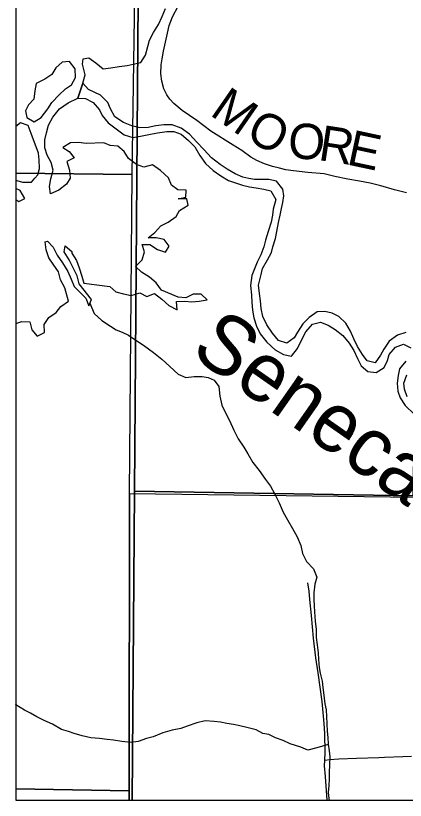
# Model space of a CAD drawing. Extents: x 0 to 191, y 0 to 55.
# Drawn here: x 184.17 to 184.796, y 47.92 to 49.18 of the extents above; entities that cross this region are included whole.
import ezdxf

# ---------------------------------------------------------------- set-up
doc = ezdxf.new("R2010")
doc.units = 0
for name, color, linetype in [('GM_X_Corporation', 7, 'Continuous'), ('GM_X_County_Road', 7, 'Continuous'), ('GM_X_County_Road_Text', 7, 'Continuous'), ('GM_X_Major_Lake', 7, 'Continuous'), ('GM_X_Minor_River', 7, 'Continuous'), ('GM_X_Minor_River_Text', 7, 'Continuous')]:
    doc.layers.add(name, color=color, linetype=linetype)

msp = doc.modelspace()

# ---------------------------------------------------------------- linework, layer by layer
at = {"layer": 'GM_X_Corporation'}
for points in [[(184.1701, 53.923), (184.1701, 47.9197), (186.2932, 47.9197), (186.2941, 48.012), (186.2991, 48.3871), (186.4921, 48.3828), (187.098, 48.377), (187.7625, 48.3707), (187.7657, 48.3707), (188.3304, 48.3653), (188.401, 48.3646), (188.9117, 48.3542), (189.3607, 48.345), (189.6849, 48.3383), (190.1514, 48.3336), (190.3574, 48.3286), (190.3641, 48.8031), (190.3751, 50.4761)], [(184.1701, 53.923), (184.1701, 49.9388), (184.171, 49.9388), (184.1826, 49.9387), (184.1847, 49.9387), (184.3733, 49.937), (184.3701, 49.6407), (184.3701, 49.6374), (184.3608, 48.4162), (184.8085, 48.4088), (184.8161, 48.8829), (184.8161, 48.8869), (184.8319, 50.3441), (184.8319, 50.3472), (184.8438, 50.7018)]]:
    msp.add_lwpolyline(points, dxfattribs=at)
for points in [[(184.1701, 49.9388), (184.1701, 47.9197), (184.357, 47.9197), (184.3608, 48.4162), (184.3701, 49.6374), (184.3701, 49.6407), (184.3733, 49.937), (184.1847, 49.9387), (184.1826, 49.9387), (184.171, 49.9388)], [(184.1701, 49.9382), (184.1701, 48.9269), (184.3573, 48.9248), (184.3647, 49.4297), (184.3713, 49.9361)], [(184.3647, 49.4297), (185.276, 49.4114), (185.2748, 48.3999), (184.3526, 48.412), (184.3573, 48.9248)], [(184.1701, 48.9269), (184.1701, 47.938), (184.3521, 47.9349), (184.3526, 48.412), (184.3573, 48.9248)], [(184.3521, 47.9197), (185.2718, 47.9197), (185.2748, 48.3999), (184.3526, 48.412), (184.3521, 47.9349)], [(184.357, 47.9197), (186.2932, 47.9197), (186.2941, 48.012), (186.2991, 48.3871), (186.1484, 48.3893), (186.1442, 48.3893), (185.2112, 48.4029), (185.207, 48.403), (184.8085, 48.4088), (184.3608, 48.4162)], [(184.1701, 47.938), (184.1701, 47.9197), (184.3521, 47.9197), (184.3521, 47.9349)]]:
    msp.add_lwpolyline(points, close=True, dxfattribs=at)
at = {"layer": 'GM_X_County_Road'}
for points in [[(184.7978, 48.8952), (184.7783, 48.9001), (184.7566, 48.9062), (184.7392, 48.9105), (184.7223, 48.9137), (184.7035, 48.9173), (184.6826, 48.9214), (184.6652, 48.9254), (184.6391, 48.9279), (184.6161, 48.9305), (184.6037, 48.9323), (184.5937, 48.9345), (184.5824, 48.9374), (184.5694, 48.9415), (184.5573, 48.9471), (184.5476, 48.9526), (184.533, 48.9631), (184.5191, 48.9717), (184.4835, 48.994), (184.4611, 49.0112), (184.4375, 49.0276), (184.4239, 49.0387), (184.4178, 49.0458), (184.4127, 49.0526), (184.4081, 49.062), (184.4048, 49.0742), (184.403, 49.086), (184.4036, 49.1008), (184.4052, 49.1102), (184.4072, 49.1225), (184.4139, 49.1513), (184.4164, 49.1636), (184.4218, 49.1779), (184.4399, 49.2127)], [(184.6667, 47.9844), (184.6668, 47.9967), (184.6663, 48.0271), (184.6654, 48.0429), (184.6621, 48.0783), (184.6559, 48.1245), (184.6522, 48.1487), (184.6483, 48.18), (184.6448, 48.2162), (184.6423, 48.2422), (184.6412, 48.2553), (184.6391, 48.269)], [(184.6667, 47.9844), (184.6743, 47.9854), (184.6892, 47.9865), (184.7174, 47.9871), (184.753, 47.9887), (184.7625, 47.9892), (184.7918, 47.9903), (184.8054, 47.9906)], [(184.6703, 47.9197), (184.6676, 47.9579), (184.6661, 47.9749), (184.6667, 47.9844)]]:
    msp.add_lwpolyline(points, dxfattribs=at)
at = {"layer": 'GM_X_Major_Lake'}
for p, q in [((184.27, 49.0471), (184.2779, 49.0715)), ((184.2794, 48.7499), (184.321, 48.7447))]:
    msp.add_line(p, q, dxfattribs=at)
for points in [[(184.2783, 49.1101), (184.2875, 49.112), (184.2989, 49.1041), (184.3107, 49.0942), (184.3228, 49.0958), (184.3361, 49.0981), (184.349, 49.0996), (184.3585, 49.1019), (184.371, 49.1042), (184.3786, 49.1163), (184.3823, 49.13), (184.385, 49.1403), (184.3914, 49.1524), (184.3994, 49.1653), (184.4054, 49.1782), (184.4107, 49.1911)], [(184.2551, 49.0654), (184.2597, 49.0687), (184.2662, 49.0805), (184.2654, 49.0942), (184.2562, 49.1059), (184.2449, 49.1051), (184.2343, 49.096), (184.2282, 49.0853), (184.2168, 49.0777), (184.2032, 49.0708), (184.2006, 49.0591), (184.1991, 49.0458), (184.1904, 49.0363), (184.1858, 49.0268)], [(184.2779, 49.0715), (184.2817, 49.0848), (184.2773, 49.1018), (184.2783, 49.1101)], [(184.1858, 49.0268), (184.1878, 49.0161), (184.1995, 49.0093), (184.2109, 49.0162), (184.2219, 49.0299), (184.2283, 49.0402), (184.2397, 49.0524), (184.2503, 49.0619), (184.2551, 49.0654)], [(184.4042, 48.7391), (184.3954, 48.7505), (184.3848, 48.7596), (184.3723, 48.7675), (184.3624, 48.7766), (184.373, 48.7873), (184.3768, 48.8002), (184.373, 48.8123), (184.3855, 48.8123), (184.3977, 48.8044), (184.4106, 48.7999), (184.4163, 48.8094), (184.4087, 48.8203), (184.3958, 48.823), (184.3829, 48.823), (184.3935, 48.8317), (184.403, 48.8424), (184.4151, 48.8481), (184.428, 48.8572), (184.4333, 48.8667), (184.447, 48.8754), (184.4447, 48.8853), (184.431, 48.8857), (184.4435, 48.888), (184.4439, 48.8993), (184.4306, 48.8997), (184.4204, 48.9073), (184.4155, 48.919), (184.4025, 48.9308), (184.3896, 48.9399), (184.376, 48.9364), (184.3639, 48.9406), (184.351, 48.9501), (184.3441, 48.9614), (184.3343, 48.9701), (184.3217, 48.9709), (184.3115, 48.9754), (184.2834, 48.9746), (184.2709, 48.9757), (184.258, 48.9753), (184.2459, 48.9677), (184.2561, 48.9617), (184.2641, 48.9514), (184.252, 48.9457), (184.2565, 48.9317), (184.2577, 48.9188), (184.2516, 48.9093), (184.2391, 48.8994), (184.2258, 48.8937), (184.2243, 48.9051), (184.2266, 48.9176), (184.2304, 48.9313), (184.2269, 48.9438), (184.2205, 48.9556), (184.2171, 48.9673), (184.2171, 48.9802), (184.2197, 48.9916), (184.2227, 49.0038), (184.2296, 49.0167), (184.2402, 49.03), (184.2542, 49.0399), (184.27, 49.0471)], [(184.2009, 48.9186), (184.2058, 48.9243), (184.2081, 48.9342), (184.2076, 48.9479), (184.2065, 48.9589), (184.203, 48.9691), (184.1988, 48.9801), (184.195, 48.9903), (184.1901, 49.0032), (184.1779, 49.0074), (184.1701, 49.0019)], [(184.1701, 48.916), (184.1717, 48.9151), (184.1812, 48.9121), (184.1956, 48.9125), (184.2009, 48.9186)], [(184.181, 48.8926), (184.1774, 48.8988), (184.1701, 48.9022)], [(184.1701, 48.8847), (184.1752, 48.8813), (184.1846, 48.8863), (184.181, 48.8926)], [(184.2172, 48.8163), (184.2213, 48.8174), (184.2304, 48.8079), (184.2369, 48.795), (184.2452, 48.7825), (184.2536, 48.7689), (184.2593, 48.7567), (184.2642, 48.7446)], [(184.2491, 48.7427), (184.2422, 48.7556), (184.2388, 48.7685), (184.2301, 48.7806), (184.2232, 48.7905), (184.2191, 48.8034), (184.2172, 48.8163)], [(184.2718, 48.7488), (184.2688, 48.7617), (184.2559, 48.7875), (184.2479, 48.8004), (184.2494, 48.8102), (184.2604, 48.8008)], [(184.2604, 48.8008), (184.2604, 48.7985), (184.2676, 48.7864), (184.2722, 48.7746), (184.276, 48.7613), (184.2794, 48.7499)], [(184.2642, 48.7446), (184.2827, 48.7259), (184.2874, 48.7135), (184.2918, 48.7241), (184.2718, 48.7488)], [(184.1701, 48.6854), (184.1798, 48.6887), (184.1927, 48.6878), (184.1959, 48.6749), (184.2044, 48.6652), (184.2161, 48.671), (184.2159, 48.6839), (184.2233, 48.695), (184.2353, 48.7032), (184.2427, 48.7128), (184.2551, 48.7213), (184.2491, 48.7427)], [(184.321, 48.7447), (184.3306, 48.7361), (184.3432, 48.7329), (184.3557, 48.7304), (184.3693, 48.7344), (184.3804, 48.7285), (184.3932, 48.7336), (184.4047, 48.7243), (184.4162, 48.7142), (184.4291, 48.7072), (184.4282, 48.7205), (184.4414, 48.7211), (184.4528, 48.7201), (184.4645, 48.7214), (184.4774, 48.7231), (184.4678, 48.7325), (184.4553, 48.7323), (184.4433, 48.7264), (184.4307, 48.7277), (184.4042, 48.7391)]]:
    msp.add_lwpolyline(points, dxfattribs=at)
at = {"layer": 'GM_X_Minor_River'}
msp.add_line((184.2779, 49.0715), (184.27, 49.0471), dxfattribs=at)
for points in [[(184.5599, 48.7467), (184.564, 48.7638), (184.5666, 48.7736), (184.5745, 48.7873), (184.5806, 48.7991), (184.5828, 48.8086), (184.587, 48.8219), (184.5896, 48.8333), (184.5919, 48.8474), (184.5945, 48.8595), (184.5967, 48.8698), (184.599, 48.8797), (184.6009, 48.8903), (184.599, 48.9009), (184.5891, 48.9138), (184.5765, 48.9168), (184.5538, 48.9167), (184.5443, 48.9182), (184.5348, 48.9204), (184.5226, 48.9257), (184.5097, 48.9329), (184.4983, 48.9404), (184.4843, 48.9514), (184.4721, 48.9647), (184.4607, 48.9764), (184.4489, 48.9896), (184.4356, 48.9991), (184.4215, 49.0044), (184.4082, 49.0043), (184.3953, 49.0027), (184.3828, 49.0001), (184.3692, 48.9996), (184.3563, 49.0026), (184.343, 49.0079), (184.3293, 49.0173), (184.3224, 49.0302), (184.3179, 49.0401), (184.3061, 49.0522), (184.2871, 49.0612), (184.2779, 49.0715)], [(184.27, 49.0471), (184.2822, 49.0468), (184.2947, 49.0404), (184.3046, 49.0286), (184.3088, 49.0192), (184.3183, 49.0074), (184.3316, 48.998), (184.3442, 48.9882), (184.3582, 48.984), (184.3707, 48.986), (184.384, 48.989), (184.3976, 48.9917), (184.4128, 48.9937), (184.4242, 48.9937), (184.436, 48.9892), (184.4478, 48.9794), (184.4577, 48.9692), (184.466, 48.9551), (184.4748, 48.9423), (184.487, 48.9309), (184.4995, 48.9222), (184.512, 48.9147), (184.5246, 48.9105), (184.5341, 48.9075), (184.5454, 48.9049), (184.5561, 48.903), (184.5686, 48.9012), (184.58, 48.8982), (184.5876, 48.8842), (184.5835, 48.869), (184.5827, 48.8595), (184.5801, 48.8481), (184.5756, 48.8329), (184.5711, 48.8192), (184.5684, 48.8082), (184.5639, 48.7957), (184.5579, 48.7839), (184.5533, 48.7732), (184.5492, 48.7622), (184.5473, 48.7465)], [(184.5473, 48.7465), (184.5489, 48.7311), (184.549, 48.7189), (184.5502, 48.7068), (184.5525, 48.6943), (184.5568, 48.6811), (184.5625, 48.6686), (184.5736, 48.6554), (184.5865, 48.6429), (184.6002, 48.6358), (184.6131, 48.6328), (184.6228, 48.6454), (184.6288, 48.6587), (184.6359, 48.6717), (184.6468, 48.6842), (184.6593, 48.6873), (184.6718, 48.6825), (184.6832, 48.6757), (184.6954, 48.6663), (184.7057, 48.6539), (184.7129, 48.6421), (184.7187, 48.6293), (184.7248, 48.6172), (184.7355, 48.6081), (184.7491, 48.6067), (184.7615, 48.6147), (184.7672, 48.6261), (184.7698, 48.6356), (184.7799, 48.6475), (184.7927, 48.6521), (184.8045, 48.6465)], [(184.7964, 48.6711), (184.7832, 48.6668), (184.77, 48.6569), (184.7614, 48.6443), (184.7561, 48.6344), (184.7475, 48.6219), (184.7346, 48.6252), (184.727, 48.6358), (184.719, 48.6486), (184.7128, 48.6607), (184.7078, 48.6728), (184.7002, 48.6861), (184.6888, 48.6966), (184.6782, 48.7019), (184.6664, 48.7045), (184.6543, 48.704), (184.6411, 48.6952), (184.6313, 48.6849), (184.6227, 48.6716), (184.6174, 48.6621), (184.6054, 48.6536), (184.5921, 48.6581), (184.5822, 48.6698), (184.5734, 48.683), (184.5669, 48.6963), (184.5642, 48.7095), (184.5634, 48.7217), (184.5618, 48.7336), (184.5599, 48.7467)], [(184.2893, 48.7181), (184.2963, 48.7015), (184.3084, 48.6902), (184.3221, 48.6812), (184.3316, 48.6752), (184.3411, 48.6714), (184.3513, 48.6666), (184.3631, 48.6587), (184.3753, 48.6504), (184.3916, 48.6387), (184.4049, 48.6278), (184.4175, 48.6161), (184.4312, 48.6037), (184.4433, 48.5984), (184.4566, 48.6), (184.4694, 48.6001), (184.4793, 48.5987), (184.4888, 48.5945), (184.4964, 48.584), (184.4976, 48.5688), (184.5011, 48.5544), (184.5076, 48.5408), (184.5134, 48.5298), (184.5206, 48.5143), (184.5272, 48.5003), (184.5363, 48.4867), (184.5428, 48.4761), (184.5509, 48.4621), (184.5608, 48.4493), (184.5711, 48.435), (184.5791, 48.424), (184.5863, 48.4111), (184.5929, 48.3971), (184.5998, 48.3824), (184.6066, 48.3699), (184.6143, 48.3563), (184.6223, 48.3427), (184.6277, 48.3287), (184.6304, 48.3162), (184.6373, 48.3033), (184.6484, 48.2913), (184.6537, 48.278), (184.6504, 48.2666), (184.649, 48.253), (184.6486, 48.2419), (184.6491, 48.2321), (184.6499, 48.2222), (184.6507, 48.2074), (184.6523, 48.1942), (184.6528, 48.1813), (184.654, 48.1691), (184.6556, 48.1566), (184.6564, 48.146), (184.6576, 48.1331), (184.6588, 48.1237), (184.6623, 48.1112), (184.6635, 48.1009), (184.6647, 48.0884), (184.6666, 48.0744), (184.6686, 48.0649), (184.669, 48.0543), (184.6695, 48.0425), (184.6703, 48.0308), (184.6715, 48.0206), (184.6719, 48.0099), (184.6735, 47.9993), (184.6747, 47.9895), (184.674, 47.9766), (184.6737, 47.9644), (184.6734, 47.9542), (184.6727, 47.9436), (184.6716, 47.9322), (184.6728, 47.9227), (184.6733, 47.9197)], [(184.7963, 48.6248), (184.7865, 48.6126), (184.784, 48.6016), (184.7825, 48.5894), (184.7837, 48.5766), (184.7876, 48.566), (184.7956, 48.5535), (184.8101, 48.5399)], [(184.7989, 48.5675), (184.7943, 48.5797), (184.7931, 48.5895), (184.7983, 48.6028)], [(184.672, 48.0094), (184.6534, 48.0038), (184.6391, 48.0003), (184.6277, 48.0051), (184.611, 48.0103), (184.5996, 48.0156), (184.5875, 48.0201), (184.5768, 48.0253), (184.567, 48.0271), (184.5564, 48.0328), (184.5412, 48.0365), (184.5302, 48.0394), (184.52, 48.0413), (184.509, 48.0431), (184.4991, 48.0453), (184.4885, 48.046), (184.4741, 48.0475), (184.4609, 48.044), (184.4454, 48.0386), (184.4352, 48.0351), (184.4212, 48.0324), (184.4065, 48.0281), (184.391, 48.0216), (184.3801, 48.0192), (184.3665, 48.0142), (184.3547, 48.0126), (184.3407, 48.0141), (184.3271, 48.0162), (184.3169, 48.0173), (184.3044, 48.0188), (184.2907, 48.0202), (184.2767, 48.0232), (184.2642, 48.0269), (184.2547, 48.0302), (184.2437, 48.0332), (184.2289, 48.0422), (184.216, 48.0478), (184.2042, 48.0535), (184.194, 48.0598), (184.1841, 48.0647), (184.1704, 48.073), (184.1701, 48.0733)]]:
    msp.add_lwpolyline(points, dxfattribs=at)

# ---------------------------------------------------------------- texts
at = {"layer": 'GM_X_County_Road_Text'}
for s, rotation, p in [('M', 325.2654, (184.4802, 49.021)), ('O', 331.9667, (184.5371, 48.9821)), ('O', 355.8412, (184.6059, 48.9515)), ('R', 351.2782, (184.6546, 48.948)), ('E', 347.9454, (184.6999, 48.9411))]:
    msp.add_text(s, height=0.0568, rotation=rotation, dxfattribs=at).set_placement(p)
at = {"layer": 'GM_X_Minor_River_Text'}
msp.add_text('Seneca', height=0.09469, rotation=325.0067, dxfattribs=at).set_placement((184.4482, 48.6362))

doc.saveas('drawing.dxf')
